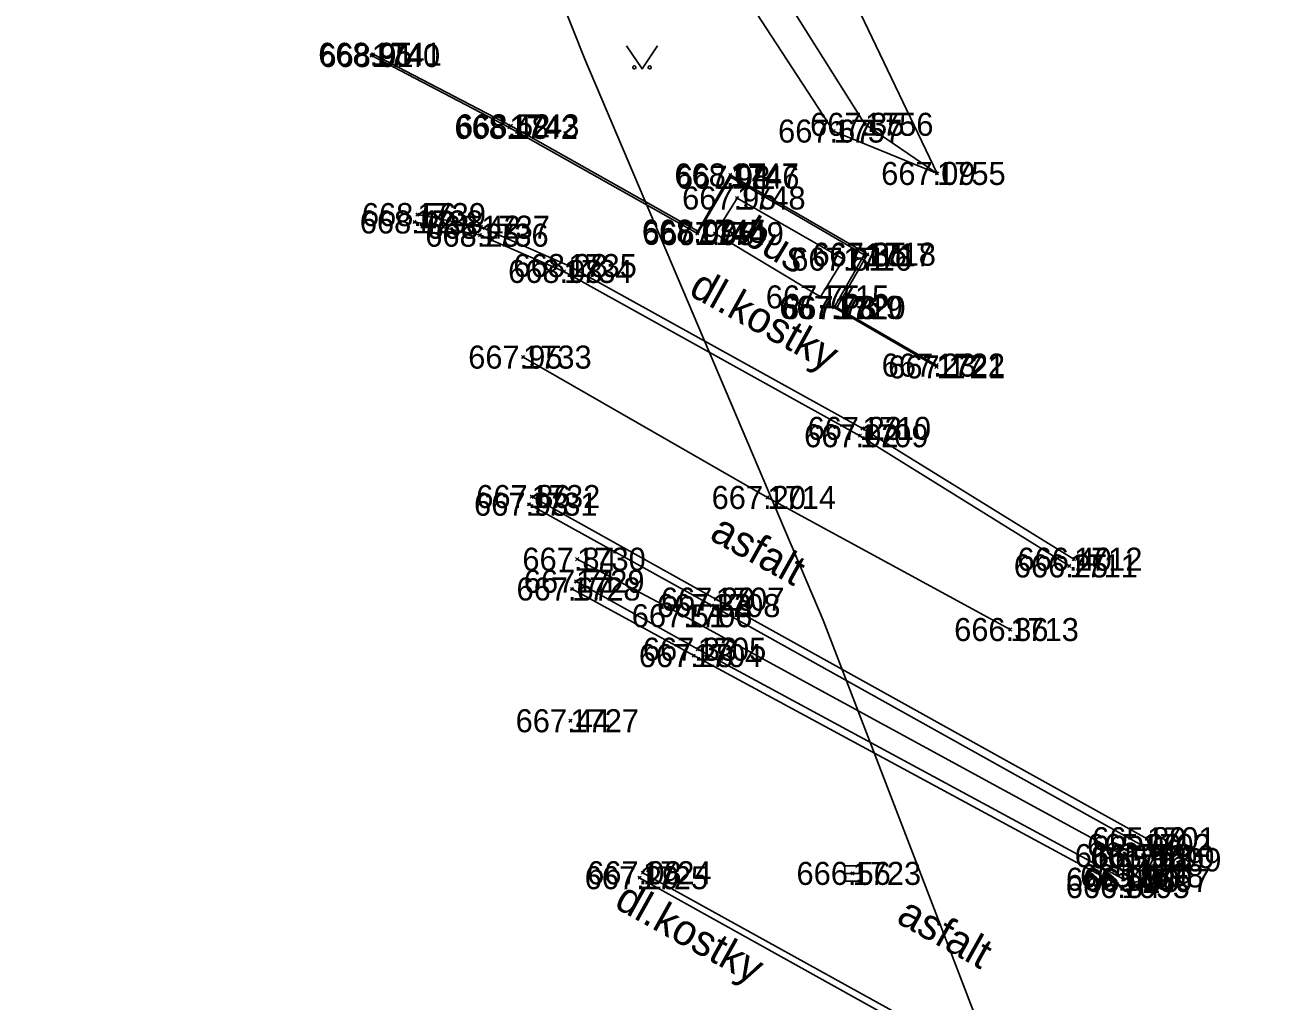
# Model space of a CAD drawing. Extents: x -844765 to -843273, y -997542 to -995529.
# Drawn here: x -844333.5 to -844293.15, y -996541.86 to -996510.07 of the extents above; entities that cross this region are included whole.
import ezdxf

# ---------------------------------------------------------------- set-up
doc = ezdxf.new("R2010")
doc.units = 0
for name, color, linetype in [('Betonový strop', 7, 'Continuous'), ('Dno', 7, 'Continuous'), ('Doplněk polohopisu', 7, 'Continuous'), ('Klenba', 7, 'Continuous'), ('Osa', 7, 'Continuous'), ('Sítě podzemní nerozlišené', 7, 'Continuous'), ('Vrstva 1', 7, 'Continuous'), ('Výška', 7, 'Continuous'), ('Číslo bodu', 7, 'Continuous'), ('Řezy', 7, 'Continuous')]:
    doc.layers.add(name, color=color, linetype=linetype)

msp = doc.modelspace()

# ---------------------------------------------------------------- linework, layer by layer
at = {"layer": 'Betonový strop'}
for points in [[(-844404.93, -996283.34), (-844395.11, -996309.68), (-844387.94, -996327.01), (-844379.85, -996344.2), (-844371.07, -996360.2), (-844364.36, -996372.36), (-844358.52, -996383.56), (-844354.38, -996391.33), (-844352.44, -996396.02), (-844349.46, -996404.19), (-844343.93, -996420.42), (-844339.33, -996436.37), (-844332.8, -996453.78), (-844328.44, -996463.53), (-844323.26, -996475.43), (-844318.3, -996486.1), (-844308.54, -996505.05), (-844303.82, -996514.91)], [(-844322.22, -996511.07), (-844317.74, -996513.41), (-844311.62, -996516.86), (-844310.53, -996515.03), (-844306.19, -996517.56), (-844307.17, -996519.27), (-844303.84, -996521.21)], [(-844303.84, -996521.15), (-844307.08, -996519.28), (-844306.09, -996517.54), (-844310.55, -996514.96), (-844311.61, -996516.79), (-844317.69, -996513.36), (-844322.17, -996511.03)], [(-844299.37, -996527.47), (-844306.25, -996523.21), (-844315.82, -996517.91), (-844318.65, -996516.66), (-844320.73, -996516.25)], [(-844320.82, -996516.49), (-844318.69, -996516.92), (-844315.96, -996518.1), (-844306.33, -996523.45), (-844299.52, -996527.69)], [(-844301.44, -996529.76), (-844309.34, -996525.46), (-844317.29, -996520.89)], [(-844317.01, -996525.43), (-844311.02, -996528.77), (-844296.99, -996536.57), (-844296.8, -996537.26), (-844297.18, -996537.93), (-844297.83, -996538.13), (-844311.74, -996530.61), (-844315.7, -996528.44)], [(-844315.57, -996528.19), (-844311.61, -996530.4), (-844297.76, -996537.89), (-844297.38, -996537.78), (-844297.03, -996537.16), (-844297.15, -996536.79), (-844311.15, -996528.98), (-844317.1, -996525.68)], [(-844315.53, -996527.47), (-844312.06, -996529.31), (-844297.75, -996537.12)], [(-844297.76, -996537.89), (-844297.75, -996537.12), (-844297.15, -996536.79)], [(-844297.38, -996537.78), (-844297.75, -996537.12), (-844297.75, -996537.12), (-844297.03, -996537.16)], [(-844313.39, -996537.68), (-844300.05, -996545.06), (-844293.86, -996547.8)], [(-844293.97, -996548.02), (-844300.17, -996545.27), (-844313.5, -996537.84)]]:
    msp.add_lwpolyline(points, dxfattribs=at)
at = {"layer": 'Dno'}
msp.add_lwpolyline([(-844313.921, -996510.756), (-844313.421, -996511.506), (-844312.921, -996510.756)], dxfattribs=at)
for centre in [(-844313.671, -996511.456), (-844313.171, -996511.456)]:
    msp.add_circle(centre, 0.05, dxfattribs=at)
at = {"layer": 'Doplněk polohopisu'}
msp.add_line((-844306.82, -996537.7), (-844306.32, -996537.7), dxfattribs=at)
msp.add_lwpolyline([(-844306.82, -996537.95), (-844306.32, -996537.95), (-844306.32, -996537.45), (-844306.82, -996537.45)], close=True, dxfattribs=at)
at = {"layer": 'Klenba'}
for p, q in [((-844310.33, -996515.71), (-844311.04, -996516.87)), ((-844306.87, -996517.7), (-844310.33, -996515.71)), ((-844311.04, -996516.87), (-844307.61, -996518.93)), ((-844307.61, -996518.93), (-844306.87, -996517.7))]:
    msp.add_line(p, q, dxfattribs=at)
at = {"layer": 'Osa'}
for p, q in [((-844306.17, -996513.31), (-844310.34, -996506.65)), ((-844307.19, -996513.53), (-844311.26, -996507.28)), ((-844303.82, -996514.91), (-844306.17, -996513.31)), ((-844303.82, -996514.91), (-844307.19, -996513.53))]:
    msp.add_line(p, q, dxfattribs=at)
msp.add_lwpolyline([(-844256.985, -996614.3), (-844264.955, -996604.805), (-844272.513, -996594.138), (-844280.435, -996583.425), (-844282.85, -996581.055), (-844288.34, -996572.812), (-844293.83, -996564.57), (-844300.425, -996547.97), (-844303.975, -996538.71), (-844307.525, -996529.45), (-844315.28, -996511.19), (-844322.67, -996492.595), (-844328.875, -996473.55)], dxfattribs=at)
at = {"layer": 'Sítě podzemní nerozlišené'}
for p, q in [((-844322.22, -996511.07), (-844322.27, -996511.02)), ((-844322.22, -996511.07), (-844322.27, -996511.12)), ((-844322.17, -996511.03), (-844322.22, -996510.98)), ((-844322.22, -996511.07), (-844322.17, -996511.02)), ((-844322.17, -996511.03), (-844322.22, -996511.08)), ((-844322.22, -996511.07), (-844322.17, -996511.12)), ((-844322.17, -996511.03), (-844322.12, -996510.98)), ((-844322.17, -996511.03), (-844322.12, -996511.08)), ((-844317.74, -996513.41), (-844317.79, -996513.36)), ((-844317.74, -996513.41), (-844317.79, -996513.46)), ((-844317.69, -996513.36), (-844317.74, -996513.31)), ((-844317.74, -996513.41), (-844317.69, -996513.36)), ((-844317.69, -996513.36), (-844317.74, -996513.41)), ((-844317.74, -996513.41), (-844317.69, -996513.46)), ((-844317.69, -996513.36), (-844317.64, -996513.31)), ((-844317.69, -996513.36), (-844317.64, -996513.41)), ((-844307.19, -996513.53), (-844307.24, -996513.48)), ((-844307.19, -996513.53), (-844307.14, -996513.48)), ((-844306.17, -996513.31), (-844306.22, -996513.26)), ((-844306.17, -996513.31), (-844306.22, -996513.36)), ((-844306.17, -996513.31), (-844306.12, -996513.26)), ((-844306.17, -996513.31), (-844306.12, -996513.36)), ((-844307.19, -996513.53), (-844307.24, -996513.58)), ((-844307.19, -996513.53), (-844307.14, -996513.58)), ((-844310.55, -996514.96), (-844310.6, -996514.91)), ((-844310.55, -996514.96), (-844310.6, -996515.01)), ((-844310.53, -996515.03), (-844310.58, -996514.98)), ((-844310.53, -996515.03), (-844310.58, -996515.08)), ((-844310.55, -996514.96), (-844310.5, -996514.91)), ((-844310.55, -996514.96), (-844310.5, -996515.01)), ((-844310.53, -996515.03), (-844310.48, -996514.98)), ((-844310.53, -996515.03), (-844310.48, -996515.08)), ((-844303.82, -996514.91), (-844303.87, -996514.86)), ((-844303.82, -996514.91), (-844303.87, -996514.96)), ((-844303.82, -996514.91), (-844303.77, -996514.86)), ((-844303.82, -996514.91), (-844303.77, -996514.96)), ((-844310.33, -996515.71), (-844310.38, -996515.66)), ((-844310.33, -996515.71), (-844310.38, -996515.76)), ((-844310.33, -996515.71), (-844310.28, -996515.66)), ((-844310.33, -996515.71), (-844310.28, -996515.76)), ((-844320.73, -996516.25), (-844320.78, -996516.2)), ((-844320.73, -996516.25), (-844320.78, -996516.3)), ((-844320.73, -996516.25), (-844320.68, -996516.2)), ((-844320.73, -996516.25), (-844320.68, -996516.3)), ((-844320.82, -996516.49), (-844320.87, -996516.44)), ((-844320.82, -996516.49), (-844320.87, -996516.54)), ((-844320.82, -996516.49), (-844320.77, -996516.44)), ((-844320.82, -996516.49), (-844320.77, -996516.54)), ((-844318.65, -996516.66), (-844318.7, -996516.61)), ((-844318.65, -996516.66), (-844318.7, -996516.71)), ((-844318.65, -996516.66), (-844318.6, -996516.61)), ((-844318.65, -996516.66), (-844318.6, -996516.71)), ((-844311.61, -996516.79), (-844311.66, -996516.74)), ((-844311.61, -996516.79), (-844311.56, -996516.74)), ((-844318.69, -996516.92), (-844318.74, -996516.87)), ((-844318.69, -996516.92), (-844318.74, -996516.97)), ((-844318.69, -996516.92), (-844318.64, -996516.87)), ((-844318.69, -996516.92), (-844318.64, -996516.97)), ((-844311.62, -996516.86), (-844311.67, -996516.81)), ((-844311.62, -996516.86), (-844311.67, -996516.91)), ((-844311.61, -996516.79), (-844311.66, -996516.84)), ((-844311.62, -996516.86), (-844311.57, -996516.81)), ((-844311.62, -996516.86), (-844311.57, -996516.91)), ((-844311.61, -996516.79), (-844311.56, -996516.84)), ((-844311.04, -996516.87), (-844311.09, -996516.82)), ((-844311.04, -996516.87), (-844311.09, -996516.92)), ((-844311.04, -996516.87), (-844310.99, -996516.82)), ((-844311.04, -996516.87), (-844310.99, -996516.92)), ((-844306.19, -996517.56), (-844306.24, -996517.51)), ((-844306.19, -996517.56), (-844306.14, -996517.51)), ((-844306.09, -996517.54), (-844306.14, -996517.49)), ((-844306.09, -996517.54), (-844306.14, -996517.59)), ((-844306.09, -996517.54), (-844306.04, -996517.49)), ((-844306.09, -996517.54), (-844306.04, -996517.59)), ((-844315.82, -996517.91), (-844315.87, -996517.86)), ((-844315.82, -996517.91), (-844315.87, -996517.96)), ((-844315.82, -996517.91), (-844315.77, -996517.86)), ((-844315.82, -996517.91), (-844315.77, -996517.96)), ((-844306.87, -996517.7), (-844306.92, -996517.65)), ((-844306.87, -996517.7), (-844306.92, -996517.75)), ((-844306.87, -996517.7), (-844306.82, -996517.65)), ((-844306.87, -996517.7), (-844306.82, -996517.75)), ((-844306.19, -996517.56), (-844306.24, -996517.61)), ((-844306.19, -996517.56), (-844306.14, -996517.61)), ((-844315.96, -996518.1), (-844316.01, -996518.05)), ((-844315.96, -996518.1), (-844316.01, -996518.15)), ((-844315.96, -996518.1), (-844315.91, -996518.05)), ((-844315.96, -996518.1), (-844315.91, -996518.15)), ((-844307.61, -996518.93), (-844307.66, -996518.88)), ((-844307.61, -996518.93), (-844307.66, -996518.98)), ((-844307.61, -996518.93), (-844307.56, -996518.88)), ((-844307.61, -996518.93), (-844307.56, -996518.98)), ((-844307.17, -996519.27), (-844307.22, -996519.22)), ((-844307.17, -996519.27), (-844307.22, -996519.32)), ((-844307.17, -996519.27), (-844307.12, -996519.22)), ((-844307.17, -996519.27), (-844307.12, -996519.32)), ((-844307.08, -996519.28), (-844307.13, -996519.23)), ((-844307.08, -996519.28), (-844307.13, -996519.33)), ((-844307.08, -996519.28), (-844307.03, -996519.23)), ((-844307.08, -996519.28), (-844307.03, -996519.33)), ((-844317.29, -996520.89), (-844317.34, -996520.84)), ((-844317.29, -996520.89), (-844317.34, -996520.94)), ((-844317.29, -996520.89), (-844317.24, -996520.84)), ((-844317.29, -996520.89), (-844317.24, -996520.94)), ((-844303.84, -996521.15), (-844303.89, -996521.1)), ((-844303.84, -996521.15), (-844303.89, -996521.2)), ((-844303.84, -996521.21), (-844303.89, -996521.16)), ((-844303.84, -996521.15), (-844303.79, -996521.1)), ((-844303.84, -996521.15), (-844303.79, -996521.2)), ((-844303.84, -996521.21), (-844303.79, -996521.16)), ((-844303.84, -996521.21), (-844303.89, -996521.26)), ((-844303.84, -996521.21), (-844303.79, -996521.26)), ((-844306.25, -996523.21), (-844306.3, -996523.16)), ((-844306.25, -996523.21), (-844306.2, -996523.16)), ((-844306.33, -996523.45), (-844306.38, -996523.4)), ((-844306.33, -996523.45), (-844306.38, -996523.5)), ((-844306.33, -996523.45), (-844306.28, -996523.4)), ((-844306.33, -996523.45), (-844306.28, -996523.5)), ((-844306.25, -996523.21), (-844306.3, -996523.26)), ((-844306.25, -996523.21), (-844306.2, -996523.26)), ((-844317.01, -996525.43), (-844317.06, -996525.38)), ((-844317.01, -996525.43), (-844317.06, -996525.48)), ((-844317.01, -996525.43), (-844316.96, -996525.38)), ((-844317.01, -996525.43), (-844316.96, -996525.48)), ((-844309.34, -996525.46), (-844309.39, -996525.41)), ((-844309.34, -996525.46), (-844309.39, -996525.51)), ((-844309.34, -996525.46), (-844309.29, -996525.41)), ((-844309.34, -996525.46), (-844309.29, -996525.51)), ((-844317.1, -996525.68), (-844317.15, -996525.63)), ((-844317.1, -996525.68), (-844317.15, -996525.73)), ((-844317.1, -996525.68), (-844317.05, -996525.63)), ((-844317.1, -996525.68), (-844317.05, -996525.73)), ((-844315.53, -996527.47), (-844315.58, -996527.42)), ((-844315.53, -996527.47), (-844315.58, -996527.52)), ((-844315.53, -996527.47), (-844315.48, -996527.42)), ((-844315.53, -996527.47), (-844315.48, -996527.52)), ((-844299.52, -996527.69), (-844299.57, -996527.64)), ((-844299.52, -996527.69), (-844299.47, -996527.64)), ((-844299.37, -996527.47), (-844299.42, -996527.42)), ((-844299.37, -996527.47), (-844299.42, -996527.52)), ((-844299.37, -996527.47), (-844299.32, -996527.42)), ((-844299.37, -996527.47), (-844299.32, -996527.52)), ((-844299.52, -996527.69), (-844299.57, -996527.74)), ((-844299.52, -996527.69), (-844299.47, -996527.74)), ((-844315.7, -996528.44), (-844315.75, -996528.39)), ((-844315.7, -996528.44), (-844315.75, -996528.49)), ((-844315.7, -996528.44), (-844315.65, -996528.39)), ((-844315.7, -996528.44), (-844315.65, -996528.49)), ((-844315.57, -996528.19), (-844315.62, -996528.14)), ((-844315.57, -996528.19), (-844315.62, -996528.24)), ((-844315.57, -996528.19), (-844315.52, -996528.14)), ((-844315.57, -996528.19), (-844315.52, -996528.24)), ((-844311.02, -996528.77), (-844311.07, -996528.72)), ((-844311.02, -996528.77), (-844311.07, -996528.82)), ((-844311.02, -996528.77), (-844310.97, -996528.72)), ((-844311.02, -996528.77), (-844310.97, -996528.82)), ((-844311.15, -996528.98), (-844311.2, -996528.93)), ((-844311.15, -996528.98), (-844311.2, -996529.03)), ((-844311.15, -996528.98), (-844311.1, -996528.93)), ((-844311.15, -996528.98), (-844311.1, -996529.03)), ((-844312.06, -996529.31), (-844312.11, -996529.26)), ((-844312.06, -996529.31), (-844312.11, -996529.36)), ((-844312.06, -996529.31), (-844312.01, -996529.26)), ((-844312.06, -996529.31), (-844312.01, -996529.36)), ((-844301.44, -996529.76), (-844301.49, -996529.71)), ((-844301.44, -996529.76), (-844301.49, -996529.81)), ((-844301.44, -996529.76), (-844301.39, -996529.71)), ((-844301.44, -996529.76), (-844301.39, -996529.81)), ((-844311.61, -996530.4), (-844311.66, -996530.35)), ((-844311.61, -996530.4), (-844311.66, -996530.45)), ((-844311.61, -996530.4), (-844311.56, -996530.35)), ((-844311.61, -996530.4), (-844311.56, -996530.45)), ((-844311.74, -996530.61), (-844311.79, -996530.56)), ((-844311.74, -996530.61), (-844311.79, -996530.66)), ((-844311.74, -996530.61), (-844311.69, -996530.56)), ((-844311.74, -996530.61), (-844311.69, -996530.66)), ((-844315.75, -996532.73), (-844315.8, -996532.68)), ((-844315.75, -996532.73), (-844315.8, -996532.78)), ((-844315.75, -996532.73), (-844315.7, -996532.68)), ((-844315.75, -996532.73), (-844315.7, -996532.78)), ((-844296.99, -996536.57), (-844297.04, -996536.52)), ((-844296.99, -996536.57), (-844296.94, -996536.52)), ((-844297.15, -996536.79), (-844297.2, -996536.74)), ((-844297.15, -996536.79), (-844297.2, -996536.84)), ((-844297.15, -996536.79), (-844297.1, -996536.74)), ((-844297.15, -996536.79), (-844297.1, -996536.84)), ((-844296.99, -996536.57), (-844297.04, -996536.62)), ((-844296.99, -996536.57), (-844296.94, -996536.62)), ((-844297.75, -996537.12), (-844297.8, -996537.07)), ((-844297.75, -996537.12), (-844297.8, -996537.17)), ((-844297.75, -996537.12), (-844297.7, -996537.07)), ((-844297.75, -996537.12), (-844297.7, -996537.17)), ((-844297.03, -996537.16), (-844297.08, -996537.11)), ((-844297.03, -996537.16), (-844297.08, -996537.21)), ((-844297.03, -996537.16), (-844296.98, -996537.11)), ((-844297.03, -996537.16), (-844296.98, -996537.21)), ((-844296.8, -996537.26), (-844296.85, -996537.21)), ((-844296.8, -996537.26), (-844296.85, -996537.31)), ((-844296.8, -996537.26), (-844296.75, -996537.21)), ((-844296.8, -996537.26), (-844296.75, -996537.31)), ((-844313.39, -996537.68), (-844313.44, -996537.63)), ((-844313.39, -996537.68), (-844313.44, -996537.73)), ((-844313.39, -996537.68), (-844313.34, -996537.63)), ((-844313.39, -996537.68), (-844313.34, -996537.73)), ((-844306.57, -996537.7), (-844306.62, -996537.65)), ((-844306.57, -996537.7), (-844306.62, -996537.75)), ((-844306.57, -996537.7), (-844306.52, -996537.65)), ((-844306.57, -996537.7), (-844306.52, -996537.75)), ((-844297.38, -996537.78), (-844297.43, -996537.73)), ((-844297.38, -996537.78), (-844297.33, -996537.73)), ((-844313.5, -996537.84), (-844313.55, -996537.79)), ((-844313.5, -996537.84), (-844313.55, -996537.89)), ((-844313.5, -996537.84), (-844313.45, -996537.79)), ((-844313.5, -996537.84), (-844313.45, -996537.89)), ((-844297.83, -996538.13), (-844297.88, -996538.08)), ((-844297.83, -996538.13), (-844297.88, -996538.18)), ((-844297.83, -996538.13), (-844297.78, -996538.08)), ((-844297.83, -996538.13), (-844297.78, -996538.18)), ((-844297.76, -996537.89), (-844297.81, -996537.84)), ((-844297.76, -996537.89), (-844297.81, -996537.94)), ((-844297.76, -996537.89), (-844297.71, -996537.84)), ((-844297.76, -996537.89), (-844297.71, -996537.94)), ((-844297.38, -996537.78), (-844297.43, -996537.83)), ((-844297.38, -996537.78), (-844297.33, -996537.83)), ((-844297.18, -996537.93), (-844297.23, -996537.88)), ((-844297.18, -996537.93), (-844297.23, -996537.98)), ((-844297.18, -996537.93), (-844297.13, -996537.88)), ((-844297.18, -996537.93), (-844297.13, -996537.98))]:
    msp.add_line(p, q, dxfattribs=at)

# ---------------------------------------------------------------- texts
at = {"layer": 'Vrstva 1'}
msp.add_text('bus', height=1, rotation=329.0117, dxfattribs=at).set_placement((-844310.236, -996517.104))
at = {"layer": 'Výška'}
for s, rotation, p in [('dl.kostky', 331.0217, (-844311.942, -996518.847)), ('asfalt', 330.9281, (-844311.268, -996526.806)), ('dl.kostky', 330.8652, (-844314.367, -996538.79)), ('asfalt', 330.8652, (-844305.191, -996539.277))]:
    msp.add_text(s, height=1, rotation=rotation, dxfattribs=at).set_placement(p)
at = {"layer": 'Číslo bodu'}
for s, p in [('1740', (-844322.22, -996511.445)), ('1741', (-844322.17, -996511.405)), ('1742', (-844317.74, -996513.785)), ('1743', (-844317.69, -996513.735)), ('1756', (-844306.17, -996513.685)), ('1757', (-844307.19, -996513.905)), ('1747', (-844310.55, -996515.335)), ('1746', (-844310.53, -996515.405)), ('1755', (-844303.82, -996515.285)), ('1748', (-844310.33, -996516.085)), ('1739', (-844320.73, -996516.625)), ('1738', (-844320.82, -996516.865)), ('1737', (-844318.65, -996517.035)), ('1736', (-844318.69, -996517.295)), ('1744', (-844311.62, -996517.235)), ('1745', (-844311.61, -996517.165)), ('1749', (-844311.04, -996517.245)), ('1735', (-844315.82, -996518.285)), ('1716', (-844306.87, -996518.075)), ('1717', (-844306.19, -996517.935)), ('1718', (-844306.09, -996517.915)), ('1734', (-844315.96, -996518.475)), ('1715', (-844307.61, -996519.305)), ('1719', (-844307.17, -996519.645)), ('1720', (-844307.08, -996519.655)), ('1733', (-844317.29, -996521.265)), ('1722', (-844303.84, -996521.525)), ('1721', (-844303.84, -996521.585)), ('1709', (-844306.33, -996523.825)), ('1710', (-844306.25, -996523.585)), ('1732', (-844317.01, -996525.805)), ('1714', (-844309.34, -996525.835)), ('1731', (-844317.1, -996526.055)), ('1730', (-844315.53, -996527.845)), ('1712', (-844299.37, -996527.845)), ('1711', (-844299.52, -996528.065)), ('1729', (-844315.57, -996528.565)), ('1728', (-844315.7, -996528.815)), ('1707', (-844311.02, -996529.145)), ('1708', (-844311.15, -996529.355)), ('1706', (-844312.06, -996529.685)), ('1713', (-844301.44, -996530.135)), ('1705', (-844311.61, -996530.775)), ('1704', (-844311.74, -996530.985)), ('1727', (-844315.75, -996533.105)), ('1702', (-844297.15, -996537.165)), ('1701', (-844296.99, -996536.945)), ('1703', (-844297.75, -996537.495)), ('1700', (-844297.03, -996537.535)), ('1699', (-844296.8, -996537.635)), ('1724', (-844313.39, -996538.055)), ('1723', (-844306.57, -996538.075)), ('1725', (-844313.5, -996538.215)), ('1696', (-844297.76, -996538.265)), ('1698', (-844297.38, -996538.155)), ('1697', (-844297.18, -996538.305)), ('1695', (-844297.83, -996538.505))]:
    msp.add_text(s, height=0.75, dxfattribs=at).set_placement(p)
at = {"layer": 'Řezy'}
for s, p in [('668.95', (-844323.956, -996511.405)), ('668.91', (-844323.918, -996511.445)), ('668.48', (-844319.523, -996513.785)), ('668.52', (-844319.473, -996513.735)), ('667.35', (-844307.953, -996513.685)), ('667.67', (-844308.994, -996513.905)), ('668.04', (-844312.366, -996515.335)), ('667.98', (-844312.316, -996515.405)), ('667.09', (-844305.639, -996515.285)), ('667.95', (-844312.116, -996516.085)), ('668.56', (-844322.534, -996516.625)), ('668.42', (-844322.603, -996516.865)), ('668.42', (-844320.433, -996517.035)), ('668.25', (-844320.473, -996517.295)), ('668.03', (-844313.426, -996517.165)), ('667.97', (-844313.406, -996517.235)), ('667.95', (-844312.826, -996517.245)), ('668.28', (-844317.603, -996518.285)), ('667.81', (-844308.565, -996518.075)), ('667.81', (-844307.885, -996517.935)), ('667.85', (-844307.873, -996517.915)), ('668.08', (-844317.776, -996518.475)), ('667.75', (-844309.393, -996519.305)), ('667.73', (-844308.953, -996519.645)), ('667.78', (-844308.863, -996519.655)), ('667.95', (-844319.076, -996521.265)), ('667.23', (-844305.623, -996521.525)), ('667.17', (-844305.411, -996521.585)), ('667.02', (-844308.146, -996523.825)), ('667.23', (-844308.033, -996523.585)), ('667.86', (-844318.814, -996525.805)), ('667.20', (-844311.156, -996525.835)), ('667.93', (-844318.886, -996526.055)), ('667.84', (-844317.313, -996527.845)), ('666.40', (-844301.206, -996527.845)), ('666.25', (-844301.324, -996528.065)), ('667.71', (-844317.265, -996528.565)), ('667.67', (-844317.504, -996528.815)), ('667.29', (-844312.806, -996529.145)), ('667.33', (-844312.933, -996529.355)), ('667.51', (-844313.755, -996529.685)), ('666.36', (-844303.265, -996530.135)), ('667.33', (-844313.393, -996530.775)), ('667.28', (-844313.523, -996530.985)), ('667.44', (-844317.533, -996533.105)), ('665.99', (-844298.939, -996537.165)), ('665.89', (-844298.776, -996536.945)), ('666.15', (-844299.341, -996537.495)), ('665.96', (-844298.837, -996537.535)), ('665.88', (-844298.583, -996537.635)), ('667.08', (-844315.206, -996538.055)), ('666.56', (-844308.395, -996538.075)), ('667.29', (-844315.286, -996538.215)), ('666.00', (-844299.629, -996538.265)), ('665.97', (-844299.166, -996538.155)), ('665.90', (-844298.999, -996538.305)), ('666.34', (-844299.634, -996538.505))]:
    msp.add_text(s, height=0.75, dxfattribs=at).set_placement(p)

doc.saveas('drawing.dxf')
